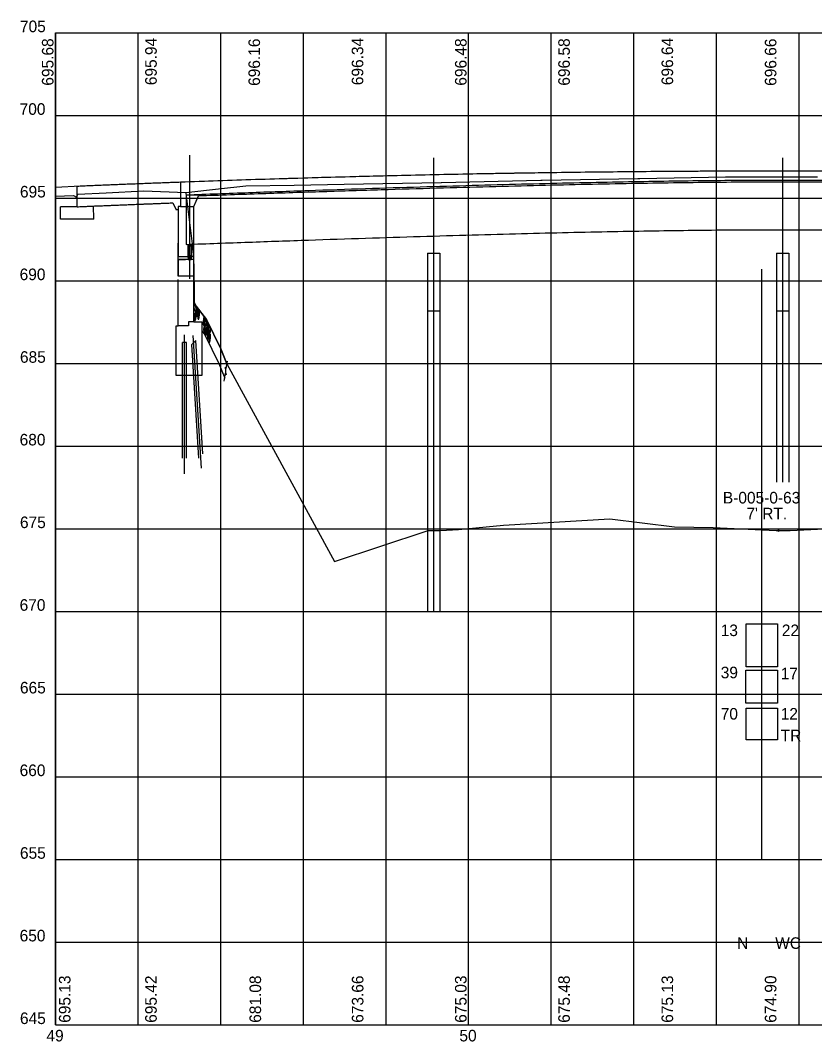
# Model space of a CAD drawing. Extents: x 991 to 1508, y 566 to 813.
# Drawn here: x 991.5 to 1183.7, y 566 to 813 of the extents above; entities that cross this region are included whole.
import ezdxf

# ---------------------------------------------------------------- set-up
doc = ezdxf.new("R2010")
doc.units = 0
for name, color, linetype in [('_CIVIL_CONSTRUCTION', 7, 'Continuous'), ('BR_P_Brg_Pad_Object', 7, 'Continuous'), ('BR_P_Dia_Object', 7, 'Continuous'), ('BR_P_Gen_Approach_Slab', 7, 'Continuous'), ('BR_P_Gen_Phase_Construction', 7, 'Continuous'), ('BR_P_Gen_Waterproofing', 7, 'Continuous'), ('BR_P_Slab_Object', 7, 'Continuous'), ('BR_P_Sub_Object', 7, 'Continuous'), ('BR_X_Beam_Object', 7, 'Continuous'), ('BR_X_Brg_Centerline', 7, 'Continuous'), ('BR_X_Gen_Porous_Backfill', 7, 'Continuous'), ('BR_X_Gen_Slope_Protection', 7, 'Continuous'), ('BR_X_Sub_Const_Joint', 7, 'Continuous'), ('BR_X_Sub_Deep_Centerline', 7, 'Continuous'), ('BR_X_Sub_Deep_Object', 7, 'Continuous'), ('BR_X_Sub_Object', 7, 'Continuous'), ('Default', 7, 'Continuous'), ('GT_Project_Text', 7, 'Continuous'), ('GT_Project_Text_2', 7, 'Continuous'), ('PF_P_Grade_Line', 7, 'Continuous'), ('PF_P_Sta_Elev_Text', 7, 'Continuous'), ('PF_P_Text_Strip_Grades_20', 7, 'Continuous'), ('PF_X_Ground_Line', 7, 'Continuous'), ('PF_X_Text_Strip_Grade', 7, 'Continuous'), ('SC_Scratch1', 7, 'Continuous'), ('SH_Major_Grid_Line', 7, 'Continuous'), ('SH_Named_Boundary', 7, 'Continuous'), ('SH_Text', 7, 'Continuous')]:
    doc.layers.add(name, color=color, linetype=linetype)

msp = doc.modelspace()

# ---------------------------------------------------------------- linework, layer by layer
at = {"layer": '_CIVIL_CONSTRUCTION'}
msp.add_ellipse((1175, 689.6), major_axis=(0, 0.2), ratio=0.25, dxfattribs=at)
at = {"layer": 'BR_P_Brg_Pad_Object'}
for p, q in [((1032.04, 758.84), (1033.04, 758.84)), ((1032.04, 758.84), (1032.04, 758.51)), ((1033.04, 758.51), (1033.04, 758.84)), ((1032.04, 758.51), (1033.04, 758.51)), ((1032.04, 756.17), (1033.04, 756.17)), ((1032.04, 756.17), (1032.04, 755.84)), ((1032.13, 756.17), (1032.13, 758.51)), ((1032.21, 756.17), (1032.21, 758.51)), ((1032.88, 756.17), (1032.88, 758.51)), ((1032.96, 756.17), (1032.96, 758.51)), ((1033.04, 755.84), (1033.04, 756.17)), ((1031.96, 755.84), (1032.96, 755.84)), ((1032.08, 755.17), (1032.83, 755.17)), ((1032.17, 755.17), (1032.17, 755.84)), ((1032.17, 755.51), (1032.92, 755.51)), ((1032.92, 755.17), (1032.92, 755.84))]:
    msp.add_line(p, q, dxfattribs=at)
at = {"layer": 'BR_P_Dia_Object'}
for p, q in [((1033.46, 768.05), (1034.6, 770.62)), ((1030.21, 768.05), (1029.71, 768.05)), ((1029.71, 768.05), (1029.71, 755.84)), ((1033.46, 755.84), (1033.46, 768.05)), ((1033.46, 755.84), (1029.71, 755.84))]:
    msp.add_line(p, q, dxfattribs=at)
at = {"layer": 'BR_P_Gen_Approach_Slab'}
for p, q in [((1005.22, 767.96), (1005.21, 772.96)), ((1028.37, 768.89), (1029.21, 767.21)), ((1001.23, 764.97), (1001.22, 767.97)), ((1005.22, 767.96), (1001.22, 767.97)), ((1009.23, 764.97), (1009.22, 768.14)), ((1029.71, 767.21), (1029.21, 767.21)), ((1009.23, 764.97), (1001.23, 764.97))]:
    msp.add_line(p, q, dxfattribs=at)
for points in [[(1005.21, 772.96), (1017.71, 773.5), (1030.21, 773.96)], [(1005.22, 767.96), (1013.06, 768.29), (1020.72, 768.6), (1028.37, 768.89)]]:
    msp.add_open_spline(points, degree=2, dxfattribs=at)
at = {"layer": 'BR_P_Gen_Phase_Construction'}
msp.add_line((1030.21, 768.05), (1033.46, 768.05), dxfattribs=at)
at = {"layer": 'BR_P_Gen_Waterproofing'}
msp.add_line((1029.63, 759.16), (1029.63, 751.19), dxfattribs=at)
at = {"layer": 'BR_P_Slab_Object'}
msp.add_line((1030.21, 773.97), (1030.21, 768.05), dxfattribs=at)
for points in [[(1030.21, 773.96), (1176.04, 779.36), (1321.87, 773.95)], [(1034.6, 770.62), (1128.92, 774.01), (1223.23, 774), (1317.55, 770.61)]]:
    msp.add_open_spline(points, degree=2, dxfattribs=at)
at = {"layer": 'BR_P_Sub_Object'}
for p, q in [((1033.46, 755.17), (1029.71, 755.17)), ((1029.71, 755.17), (1029.71, 751.19)), ((1033.46, 751.19), (1033.46, 755.17)), ((1033.46, 751.19), (1029.71, 751.19))]:
    msp.add_line(p, q, dxfattribs=at)
at = {"layer": 'BR_X_Beam_Object'}
for p, q in [((1031.63, 770.84), (1031.63, 758.84)), ((1090.04, 756.74), (1090.04, 670)), ((1093.04, 756.74), (1093.04, 670)), ((1174.54, 756.74), (1174.54, 701.35)), ((1177.54, 756.74), (1177.54, 701.35)), ((1033.45, 740.12), (1033.45, 751.19)), ((1029.7, 739.12), (1029.7, 750.32)), ((1029.2, 727.12), (1029.2, 739.12)), ((1035.45, 740.12), (1035.45, 727.12)), ((1030.7, 707.16), (1030.7, 735.12)), ((1031.7, 707.16), (1031.7, 735.12)), ((1033.93, 735.61), (1032.96, 734.63)), ((1034.68, 707.16), (1032.96, 734.63)), ((1035.65, 708.14), (1033.93, 735.61)), ((1035.45, 727.12), (1029.2, 727.12))]:
    msp.add_line(p, q, dxfattribs=at)
for points in [[(1041.48, 729.92), (1039.99, 733.55), (1036.55, 740.7), (1034.07, 743.87), (1033.45, 745.02)], [(1035.45, 737.91), (1036.17, 736.99), (1039.5, 730.06), (1040.97, 726.5)]]:
    msp.add_lwpolyline(points, dxfattribs=at)
for points in [[(1031.63, 770.84), (1125.99, 774.38), (1220.35, 774.43), (1320.45, 770.84)], [(1031.63, 758.84), (1125.99, 762.38), (1220.35, 762.43), (1320.45, 758.84)]]:
    msp.add_open_spline(points, degree=2, dxfattribs=at)
at = {"layer": 'BR_X_Brg_Centerline'}
for p, q in [((1032.54, 750.52), (1032.54, 780.43)), ((1091.54, 670), (1091.54, 779.78)), ((1176.04, 701.35), (1176.04, 779.78))]:
    msp.add_line(p, q, dxfattribs=at)
at = {"layer": 'BR_X_Gen_Porous_Backfill'}
for points in [[(1033.65, 742.96), (1033.8, 742.72), (1033.95, 742.78), (1034.01, 743.02), (1034.01, 743.44), (1033.9, 743.98), (1033.75, 744.28), (1033.6, 744.28), (1033.53, 744.04), (1033.51, 743.62), (1033.59, 743.2), (1033.66, 742.96)], [(1033.7, 741.85), (1033.64, 741.25), (1033.66, 740.65), (1033.72, 740.41), (1033.82, 740.41), (1033.96, 740.83), (1034.03, 741.43), (1034.03, 742.03), (1033.97, 742.33), (1033.87, 742.39), (1033.76, 742.09), (1033.7, 741.79)], [(1034.13, 742.91), (1034.07, 742.31), (1034.08, 741.71), (1034.14, 741.47), (1034.25, 741.47), (1034.38, 741.89), (1034.46, 742.49), (1034.46, 743.09), (1034.4, 743.39), (1034.29, 743.45), (1034.19, 743.15), (1034.13, 742.85)], [(1034.53, 742.2), (1034.47, 741.6), (1034.48, 741), (1034.54, 740.76), (1034.65, 740.76), (1034.78, 741.18), (1034.86, 741.78), (1034.86, 742.38), (1034.8, 742.68), (1034.69, 742.74), (1034.59, 742.44), (1034.53, 742.14)], [(1035.79, 740.76), (1035.73, 740.16), (1035.74, 739.56), (1035.8, 739.32), (1035.91, 739.32), (1036.04, 739.74), (1036.12, 740.34), (1036.12, 740.94), (1036.06, 741.24), (1035.95, 741.3), (1035.85, 741), (1035.79, 740.7)], [(1035.91, 738.87), (1035.85, 738.27), (1035.87, 737.67), (1035.93, 737.43), (1036.03, 737.43), (1036.17, 737.85), (1036.24, 738.45), (1036.24, 739.05), (1036.18, 739.35), (1036.08, 739.41), (1035.97, 739.11), (1035.91, 738.81)], [(1036.28, 739.33), (1036.43, 739.09), (1036.58, 739.15), (1036.64, 739.39), (1036.64, 739.81), (1036.53, 740.35), (1036.38, 740.65), (1036.23, 740.65), (1036.16, 740.41), (1036.14, 739.99), (1036.22, 739.57), (1036.29, 739.33)], [(1036.69, 739.22), (1036.63, 738.62), (1036.65, 738.02), (1036.71, 737.78), (1036.81, 737.78), (1036.95, 738.2), (1037.02, 738.8), (1037.02, 739.4), (1036.96, 739.7), (1036.86, 739.76), (1036.75, 739.46), (1036.69, 739.16)], [(1037.18, 737.79), (1037.33, 737.55), (1037.48, 737.61), (1037.54, 737.85), (1037.54, 738.27), (1037.44, 738.81), (1037.29, 739.11), (1037.14, 739.11), (1037.06, 738.87), (1037.05, 738.45), (1037.12, 738.03), (1037.2, 737.79)], [(1036.32, 738.16), (1036.26, 737.56), (1036.27, 736.96), (1036.33, 736.72), (1036.44, 736.72), (1036.57, 737.14), (1036.65, 737.74), (1036.65, 738.34), (1036.59, 738.64), (1036.48, 738.7), (1036.38, 738.4), (1036.32, 738.1)], [(1036.82, 737.32), (1036.76, 736.72), (1036.77, 736.12), (1036.83, 735.88), (1036.94, 735.88), (1037.07, 736.3), (1037.15, 736.9), (1037.15, 737.5), (1037.09, 737.8), (1036.98, 737.86), (1036.88, 737.56), (1036.82, 737.26)], [(1037.22, 736.62), (1037.16, 736.02), (1037.17, 735.42), (1037.23, 735.18), (1037.34, 735.18), (1037.47, 735.6), (1037.55, 736.2), (1037.55, 736.8), (1037.49, 737.1), (1037.38, 737.16), (1037.28, 736.86), (1037.22, 736.56)]]:
    msp.add_lwpolyline(points, dxfattribs=at)
at = {"layer": 'BR_X_Gen_Slope_Protection'}
for p, q in [((1041.27, 727.3), (1041.18, 729.14)), ((1041.18, 729.14), (1041.31, 728.78)), ((1041.31, 728.78), (1041.61, 730.57)), ((1040.82, 725.77), (1041.13, 727.66)), ((1041.13, 727.66), (1041.27, 727.3))]:
    msp.add_line(p, q, dxfattribs=at)
at = {"layer": 'BR_X_Sub_Const_Joint'}
for p, q in [((1029.71, 755.17), (1031.46, 755.17)), ((1032.2, 739.12), (1029.7, 739.12)), ((1033.45, 740.12), (1032.2, 740.12)), ((1032.2, 740.12), (1032.2, 739.12))]:
    msp.add_line(p, q, dxfattribs=at)
at = {"layer": 'BR_X_Sub_Deep_Centerline'}
for p, q in [((1031.2, 703.31), (1031.2, 736.98)), ((1035.35, 704.69), (1033.34, 736.77))]:
    msp.add_line(p, q, dxfattribs=at)
at = {"layer": 'BR_X_Sub_Deep_Object'}
msp.add_line((1031.7, 735.12), (1030.7, 735.12), dxfattribs=at)
at = {"layer": 'BR_X_Sub_Object'}
for p, q in [((1031.63, 770.84), (1035.96, 770.84)), ((1029.71, 767.07), (1029.71, 757.19)), ((1090.04, 756.74), (1093.04, 756.74)), ((1174.54, 756.74), (1177.54, 756.74)), ((1033.46, 755.17), (1031.46, 755.17)), ((1090.04, 742.74), (1093.04, 742.74)), ((1174.54, 742.74), (1177.54, 742.74)), ((1029.2, 739.12), (1029.7, 739.12)), ((1033.45, 740.12), (1035.45, 740.12))]:
    msp.add_line(p, q, dxfattribs=at)
at = {"layer": 'Default'}
msp.add_lwpolyline([(1000, 772.73), (1006.04, 773), (1016.04, 773.41), (1026.04, 773.81), (1036.04, 774.17), (1046.04, 774.52), (1056.04, 774.83), (1066.04, 775.13), (1076.04, 775.39), (1086.04, 775.63), (1096.04, 775.85), (1106.04, 776.04), (1116.04, 776.2), (1126.04, 776.34), (1136.04, 776.46), (1146.04, 776.55), (1156.04, 776.61), (1166.04, 776.65), (1176.04, 776.66), (1186.04, 776.65)], dxfattribs=at)
at = {"layer": 'PF_P_Grade_Line'}
msp.add_lwpolyline([(1000, 772.73), (1006.04, 773), (1016.04, 773.41), (1026.04, 773.81), (1036.04, 774.17), (1046.04, 774.52), (1056.04, 774.83), (1066.04, 775.13), (1076.04, 775.39), (1086.04, 775.63), (1096.04, 775.85), (1106.04, 776.04), (1116.04, 776.2), (1126.04, 776.34), (1136.04, 776.46), (1146.04, 776.55), (1156.04, 776.61), (1166.04, 776.65), (1176.04, 776.66), (1186.04, 776.65)], dxfattribs=at)
at = {"layer": 'PF_X_Ground_Line'}
for points in [[(1031.54, 771.43), (1031.55, 771.43), (1039.41, 772.27), (1046.09, 772.99), (1046.1, 772.99), (1046.1, 772.99), (1057.78, 773.21), (1069.86, 773.44), (1069.87, 773.44), (1069.88, 773.44), (1093.37, 773.84), (1093.4, 773.84), (1117.48, 774.39), (1117.82, 774.4), (1141, 774.81), (1141.44, 774.82), (1162.15, 775.17), (1162.79, 775.17), (1184.46, 775.23)], [(1000, 770.51), (1004.38, 770.68), (1005.1, 770.3), (1005.16, 770.46), (1005.4, 770.98), (1005.42, 770.98), (1012.29, 771.33), (1021.35, 771.8), (1021.37, 771.8), (1031.53, 771.43), (1031.54, 771.43), (1031.55, 771.41), (1031.55, 771.4), (1031.55, 771.39), (1031.56, 771.28), (1033.38, 756.37), (1033.55, 747.72), (1033.57, 744.79), (1034.07, 743.87), (1036.55, 740.7), (1039.99, 733.55), (1041.48, 729.92), (1067.52, 682.16), (1089.96, 689.57), (1090.07, 689.6), (1090.11, 689.6), (1090.11, 689.6), (1090.11, 689.6), (1090.11, 689.6), (1090.13, 689.6), (1090.16, 689.6), (1090.31, 689.6), (1091.67, 689.6), (1092.91, 689.6), (1093.05, 689.6), (1093.1, 689.6), (1093.11, 689.6), (1093.17, 689.6), (1093.23, 689.61), (1097.57, 689.88), (1108.41, 690.9), (1134.17, 692.48), (1149.81, 690.53), (1159.22, 690.37), (1174.46, 689.6), (1174.61, 689.6), (1174.62, 689.6), (1174.67, 689.6), (1174.8, 689.6), (1176.29, 689.6), (1177.49, 689.6), (1177.57, 689.6), (1177.59, 689.6), (1177.6, 689.6), (1177.8, 689.61), (1192.76, 690.31)]]:
    msp.add_lwpolyline(points, dxfattribs=at)
at = {"layer": 'SC_Scratch1'}
msp.add_lwpolyline([(1100, 610), (1170.99, 610), (1170.99, 752.82)], dxfattribs=at)
at = {"layer": 'SH_Major_Grid_Line'}
for p, q in [((1000, 570), (1000, 810)), ((1000, 810), (1500, 810)), ((1000, 570), (1000, 810)), ((1000, 810), (1500, 810)), ((1000, 570), (1000, 810)), ((1000, 810), (1500, 810)), ((1000, 570), (1000, 810)), ((1020, 570), (1020, 810)), ((1020, 570), (1020, 810)), ((1040, 570), (1040, 810)), ((1040, 570), (1040, 810)), ((1060, 570), (1060, 810)), ((1060, 570), (1060, 810)), ((1080, 570), (1080, 810)), ((1080, 570), (1080, 810)), ((1100, 670), (1100, 810)), ((1100, 570), (1100, 810)), ((1120, 570), (1120, 810)), ((1120, 570), (1120, 810)), ((1140, 610), (1140, 810)), ((1140, 570), (1140, 810)), ((1160, 610), (1160, 810)), ((1160, 570), (1160, 810)), ((1180, 670), (1180, 810)), ((1180, 570), (1180, 810)), ((1000, 790), (1500, 790)), ((1000, 790), (1500, 790)), ((1000, 770), (1500, 770)), ((1000, 770), (1500, 770)), ((1000, 750), (1500, 750)), ((1000, 750), (1500, 750)), ((1000, 730), (1500, 730)), ((1000, 730), (1500, 730)), ((1000, 710), (1500, 710)), ((1000, 710), (1500, 710)), ((1000, 690), (1500, 690)), ((1000, 690), (1500, 690)), ((1000, 670), (1500, 670)), ((1000, 650), (1500, 650)), ((1000, 630), (1500, 630)), ((1000, 610), (1500, 610)), ((1000, 590), (1500, 590)), ((1000, 570), (1500, 570))]:
    msp.add_line(p, q, dxfattribs=at)
at = {"layer": 'SH_Named_Boundary'}
msp.add_line((1000, 810), (1000, 570), dxfattribs=at)
at = {"layer": 'SH_Text'}
for points in [[(1167.18, 667.05), (1174.8, 667.05), (1174.8, 656.66), (1167.18, 656.66)], [(1167.08, 655.85), (1174.77, 655.85), (1174.77, 647.88), (1167.08, 647.88)], [(1167.19, 646.67), (1174.8, 646.67), (1174.8, 639.01), (1167.19, 639.01)]]:
    msp.add_lwpolyline(points, close=True, dxfattribs=at)

# ---------------------------------------------------------------- texts
at = {"layer": 'GT_Project_Text'}
for s, p in [('B-005-0-63', (1161.55, 696.16)), ('N', (1164.99, 588.39)), ('WC', (1174.22, 588.39))]:
    msp.add_text(s, height=2.8, dxfattribs=at).set_placement(p)
at = {"layer": 'GT_Project_Text_2'}
msp.add_text("7' RT.", height=2.8, dxfattribs=at).set_placement((1167.24, 692.32))
at = {"layer": 'PF_P_Sta_Elev_Text'}
for s, p in [('705', (991.39, 810.2)), ('705', (991.39, 810.2)), ('700', (991.31, 790.2)), ('700', (991.31, 790.2)), ('695', (991.39, 770.2)), ('695', (991.39, 770.2)), ('690', (991.31, 750.2)), ('690', (991.31, 750.2)), ('685', (991.39, 730.2)), ('685', (991.39, 730.2)), ('680', (991.31, 710.2)), ('680', (991.31, 710.2)), ('675', (991.39, 690.2)), ('675', (991.39, 690.2)), ('670', (991.31, 670.2)), ('670', (991.31, 670.2)), ('665', (991.39, 650.2)), ('660', (991.31, 630.2)), ('655', (991.39, 610.2)), ('650', (991.31, 590.2)), ('645', (991.39, 570.2)), ('49', (997.8, 566)), ('50', (1097.77, 566))]:
    msp.add_text(s, height=2.8, dxfattribs=at).set_placement(p)
at = {"layer": 'PF_P_Text_Strip_Grades_20'}
for s, p in [('695.68', (999.5, 797.25)), ('695.94', (1024.5, 797.37)), ('695.94', (1024.5, 797.37)), ('696.16', (1049.5, 797.2)), ('696.16', (1049.5, 797.2)), ('696.34', (1074.5, 797.37)), ('696.34', (1074.5, 797.37)), ('696.48', (1099.5, 797.25)), ('696.48', (1099.5, 797.25)), ('696.58', (1124.5, 797.25)), ('696.58', (1124.5, 797.25)), ('696.64', (1149.5, 797.37)), ('696.64', (1149.5, 797.37)), ('696.66', (1174.5, 797.2)), ('696.66', (1174.5, 797.2))]:
    msp.add_text(s, height=2.8, rotation=90, dxfattribs=at).set_placement(p)
at = {"layer": 'PF_X_Text_Strip_Grade'}
for s, p in [('695.13', (1003.62, 570.5)), ('695.42', (1024.5, 570.5)), ('681.08', (1049.76, 570.5)), ('673.66', (1074.53, 570.5)), ('675.03', (1099.5, 570.5)), ('675.48', (1124.5, 570.5)), ('675.48', (1124.5, 570.5)), ('675.13', (1149.5, 570.5)), ('674.90', (1174.5, 570.5))]:
    msp.add_text(s, height=2.8, rotation=90, dxfattribs=at).set_placement(p)
at = {"layer": 'SH_Text'}
for s, p in [('13', (1161.03, 664.07)), ('22', (1175.82, 664.07)), ('39', (1161.03, 653.86)), ('17', (1175.55, 653.62)), ('70', (1161.03, 643.87)), ('12', (1175.55, 643.87)), ('TR', (1175.55, 638.63))]:
    msp.add_text(s, height=2.8, dxfattribs=at).set_placement(p)

doc.saveas('drawing.dxf')
